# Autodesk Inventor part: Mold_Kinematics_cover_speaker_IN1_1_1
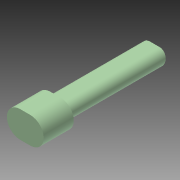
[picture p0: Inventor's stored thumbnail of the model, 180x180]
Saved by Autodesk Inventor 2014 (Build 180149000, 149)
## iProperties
Created: 2009-12
Part Number: Mold_Kinematics_cover_speaker_IN1_1_1
Document SubType Name: Modeling
Designer: gaom
Density: 1 g/cm^3
Material: Generic
Appearance: Green Pastel
Author: gaom
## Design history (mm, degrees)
node "Mold_Kinematics_cover_speaker_IN1_Base"
feature "Solid2::Mold_Kinematics_cover_speaker_IN1_Base"
tag "TaggingFeature1"
body "Solid1"
